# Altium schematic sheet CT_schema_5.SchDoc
size 266 x 267 mm
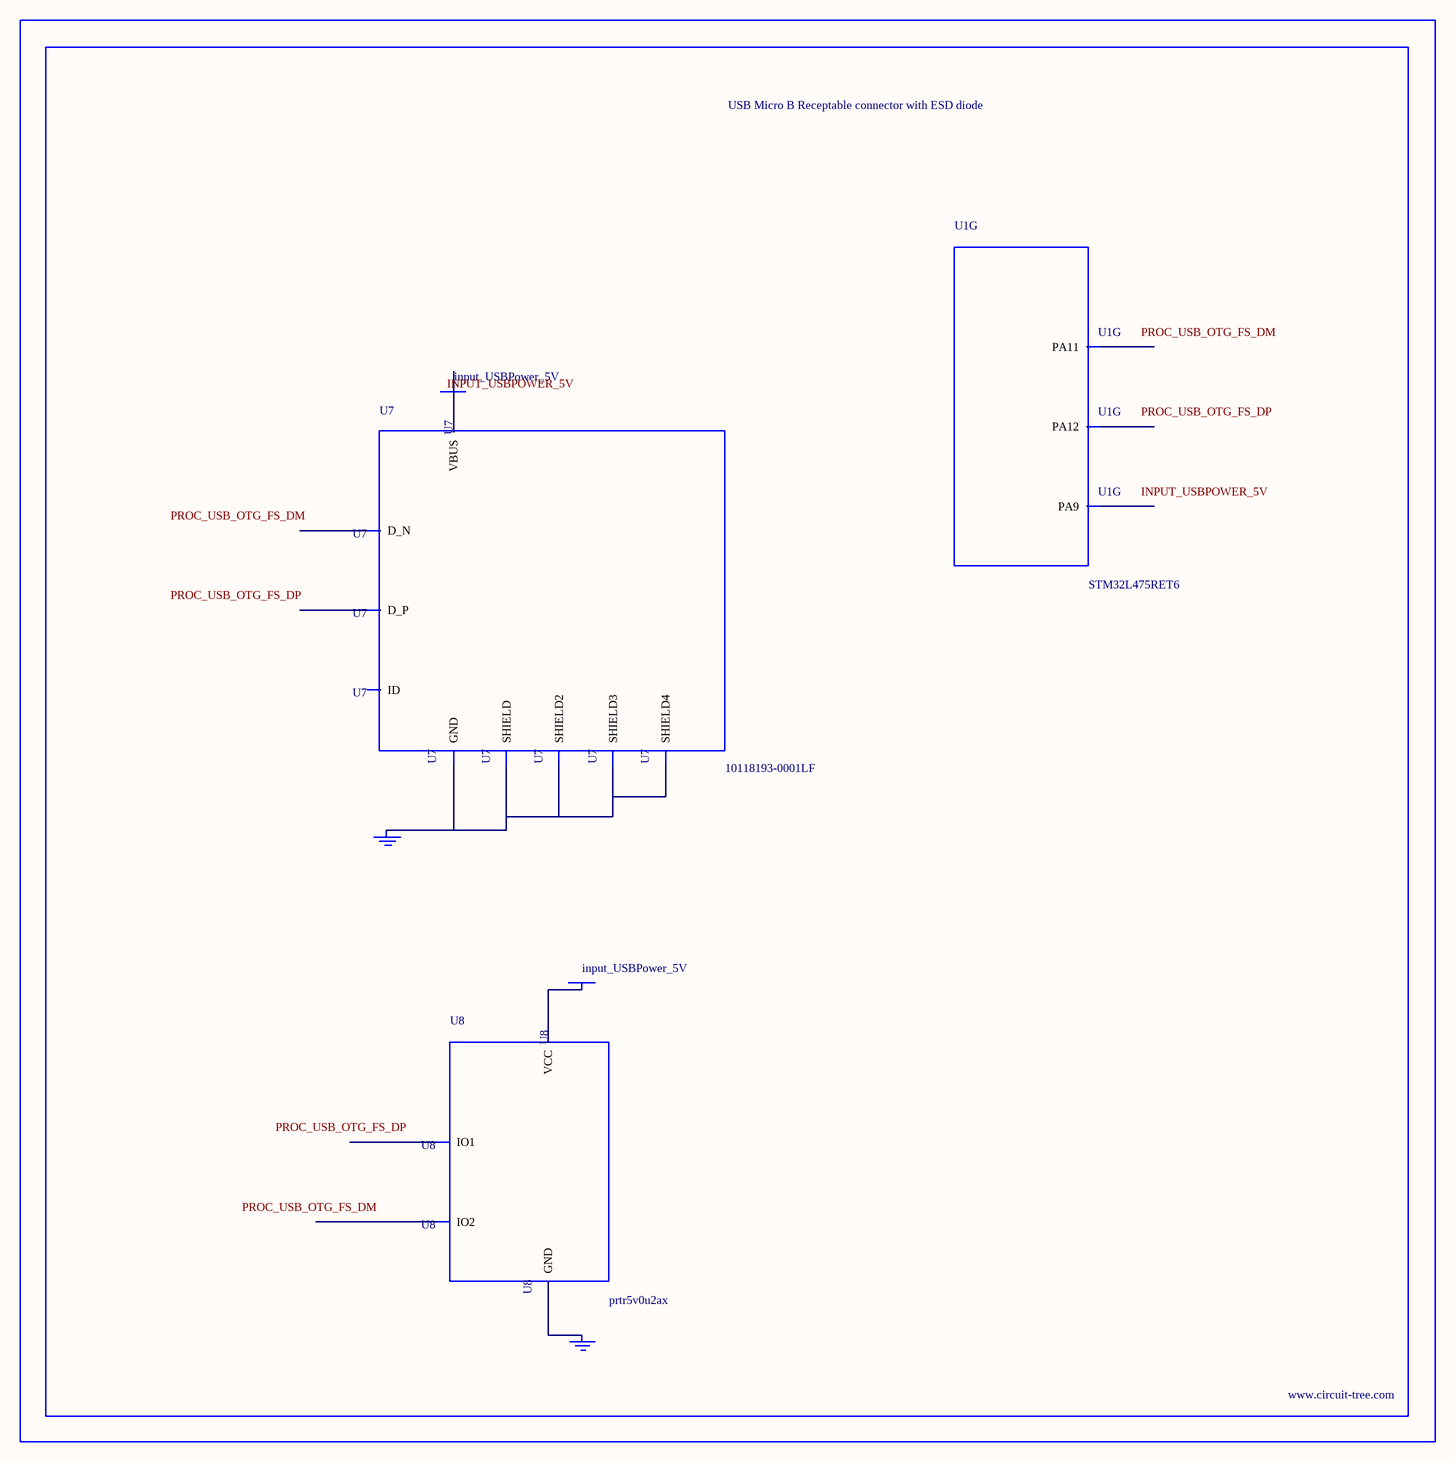
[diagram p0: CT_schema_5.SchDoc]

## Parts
BORDER4  (no value)
GND_INSTANCE_4_0  (no value)
GND_INSTANCE_4_1  (no value)
POWER_INSTANCE_4_0  input_USBPower_5V
POWER_INSTANCE_4_1  input_USBPower_5V
U1  STM32L475RET6  [LQFP64]  (part G of 8)
U7  10118193-0001LF  [FCI_10118193-0001LF]
U8  prtr5v0u2ax  [SOT143B]

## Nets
NetGND_INSTANCE_4_0_0: GND_INSTANCE_4_0.0(GND) U7.5(GND) U7.6(SHIELD) U7.7(SHIELD2) U7.8(SHIELD3) U7.9(SHIELD4)
NetGND_INSTANCE_4_1_0: GND_INSTANCE_4_1.0(GND) U8.1(GND)
NetPOWER_INSTANCE_4_0_0: POWER_INSTANCE_4_0.0(PWR) U7.1(VBUS)
NetPOWER_INSTANCE_4_1_0: POWER_INSTANCE_4_1.0(PWR) U8.4(VCC)

Not connected (* = marked no-connect by the designer): U1 42(PA9) 44(PA11) 45(PA12); U7 2(D_N) 3(D_P) 4(ID); U8 2(IO1) 3(IO2)

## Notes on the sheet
- Labels drawn without touching a wire or pin: INPUT_USBPOWER_5V, PROC_USB_OTG_FS_DM, PROC_USB_OTG_FS_DP

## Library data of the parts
BORDER4 = BORDER_PAGE4
GND_INSTANCE_4_0 GND_INSTANCE_4_1 = GND
POWER_INSTANCE_4_0 POWER_INSTANCE_4_1 = PWR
